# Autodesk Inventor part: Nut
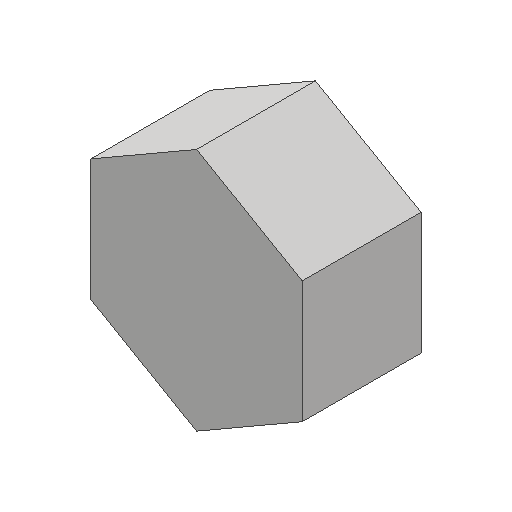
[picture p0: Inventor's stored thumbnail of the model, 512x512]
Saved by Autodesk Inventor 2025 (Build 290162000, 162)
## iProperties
Created: 2016-05
Part Number: Nut
Material: Generic
Document SubType Name: Modeling
Designer: CADCIM
Density: 1 g/cm^3
Appearance: Default
Author: CADCIM
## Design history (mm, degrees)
sketch "Sketch1"
  geometry: L1 (9.6, -5.543)-(0, -11.085); L2 (0, -11.085)-(-9.6, -5.543); L3 (-9.6, -5.543)-(-9.6, 5.543); L4 (-9.6, 5.543)-(0, 11.085); L5 (0, 11.085)-(9.6, 5.543); L6 (9.6, 5.543)-(9.6, -5.543); 2 further points
  constraints: 12 end point, 1 coincident, 1 vertical alignment, 13 other
  dimensions: "d0" = 19.2 distance between parallel lines of L3 L6
extrude "Extrusion1" new body sketch "Sketch1" distance "d1" = 10.8; taper "d2" = 0 deg
sketch "Sketch2"
  geometry: L1 (0, 11.085)-(-9.6, 5.543) reference; C1 r 9.6 at (0, 0); 1 further point
  constraints: 1 centre point, 1 coincident, 1 tangent
extrude "Extrusion2" sketch "Sketch2" distance "d3" = 10.8; taper "d4" = 60 deg
workplane "Work Plane1"
sketch "Sketch3"
  geometry: L1 (0, -11.085)-(9.6, -5.543) reference; C1 r 9.6 at (0, 0); 1 further point
  constraints: 1 centre point, 1 coincident, 1 tangent
extrude "Extrusion3" sketch "Sketch3" distance "d5" = 10.8; taper "d6" = 60 deg
hole "Hole1" diameter "d9" = 10.376; stored, may be unused: countersink angle "d13" = 90 deg, drill point angle "d15" = 118 deg; dims "d7" = 10, "d8" = 10, "d10" = 24, "d11" = 4, "d12" = 2, "d14" = 31.3
body "Solid1"
sketch "Sketch4"
  geometry: 1 further point
